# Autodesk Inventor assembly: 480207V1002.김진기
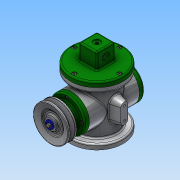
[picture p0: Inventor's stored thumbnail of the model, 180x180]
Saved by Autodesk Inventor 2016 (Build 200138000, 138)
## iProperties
Created: 2018-02
Part Number: 480207V1002.김진기
Material: 일반
Document SubType Name: Assembly
Designer: Administrator
Author: Administrator
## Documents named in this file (19)
- C:\Users\Administrator\Desktop\480207V1002.김진기\조립품.iam
- C:\Users\Administrator\Desktop\480207V1002.김진기\480207V1002.김진기.ipt
- C:\Users\Administrator\Desktop\480207V1002.김진기\뒤커버.ipt
- C:\Users\Administrator\Desktop\480207V1002.김진기\베어링 17 x 40 x 12.ipt
- C:\Users\Administrator\Desktop\480207V1002.김진기\앞커버.ipt
- C:\Users\Administrator\Desktop\480207V1002.김진기\오일 실 17 30 8.ipt
- C:\Users\Administrator\Desktop\480207V1002.김진기\덮개.ipt
- C:\Users\Administrator\Desktop\480207V1002.김진기\편심축.ipt
- C:\Users\Administrator\Desktop\480207V1002.김진기\V-벨트풀리.ipt
- C:\Users\Administrator\Desktop\480207V1002.김진기\키 4 x 4 x 12.ipt
- C:\Users\Administrator\Desktop\480207V1002.김진기\볼트 M4 x 10.ipt
- C:\Users\Administrator\Desktop\480207V1002.김진기\와셔 4x16.ipt
- C:\Users\Administrator\Desktop\480207V1002.김진기\링크.ipt
- C:\Users\Administrator\Desktop\480207V1002.김진기\슬라이더.ipt
- C:\Users\Administrator\Desktop\480207V1002.김진기\클레비스 핀 6 x 22.ipt
- 클레비스 핀 6 x 22.ipt
- C:\Users\Administrator\Desktop\480207V1002.김진기\볼트 M4 x 8.ipt
- C:\Users\Administrator\Desktop\480207V1002.김진기\E-링.ipt
- C:\Users\Administrator\Desktop\480207V1002.김진기\본체.ipt
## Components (3 placed, 3 different names)
1. 480207V1002.김진기:1 — 각도:2, 각도:4
2. V-벨트풀리:1 — 각도:3
3. E-링:1
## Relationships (3: Angle 3)
- 각도:2 [Angle]: 480207V1002.김진기:1
- 각도:3 [Angle]: V-벨트풀리:1
- 각도:4 [Angle]: 480207V1002.김진기:1
